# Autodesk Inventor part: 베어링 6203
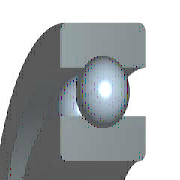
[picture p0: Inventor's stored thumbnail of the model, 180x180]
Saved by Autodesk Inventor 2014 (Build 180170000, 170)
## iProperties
IsCustomPart: 1
Created: 2012-02
Part Number: 베어링 6203
Material: 강철, 연강
Description: 깊은 그루브 볼 베어링
Document SubType Name: Modeling
Standard: KS B 2023
Designer: mduedu
Standards Organization: KS
Language: ko-KR
Size Designation: 6203 - 17 x 40 x 12
Categories: <MemberInstance><Categories><Category DisplayName="샤프트 부품" InternalName="7f7aeb1f-a693-4053-b835-cee3144e0d98" Mnemonic="SHFT"><Category DisplayName="베어링" Inter
Density: 1 g/cm^3
Appearance: Yellow
Author: mduedu
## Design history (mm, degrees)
sketch "스케치" dims "d0" = 5.98 (= -0.26 x WD + 0.26 x BD)
  geometry: L1 (3.01, 14.25)-(8.99, 14.25); L2 (6, 14.25)-(6, 11.26); L3 (6, 14.25)-(6, 17.24); L4 (3.778, 12.249)-(0, 12.249); L5 (0, 8.5)-(12, 8.5); L6 (3.778, 16.251)-(0, 16.251); L7 (0, 20)-(12, 20); L8 (12, 8.5)-(12, 12.249); L9 (8.222, 12.249)-(12, 12.249); L10 (8.222, 16.251)-(12, 16.251); L11 (12, 20)-(12, 16.251); L12 (-1.4, 0)-(8.4, 0) reference; L13 (0, -0.3)-(0, 5.3) reference
  constraints: 22 end point, 4 point on line, 2 collinear, 2 perpendicular, 2 symmetric about line, 1 midpoint, 1 parallel, 14 other
  dimensions: "d9" = 17 diameter of L5 L12 (= WD); "d11" = 40 diameter of L7 L12 (= BD); "d12" = 12 distance between parallel lines of L8 L13 (= KB); "d13" = 24.498 diameter of L9 L12 (= 0.326 x BD + 0.674 x WD)
revolve "본체" stored, may be unused: angle "d6" = 90 deg
revolve "볼" stored, may be unused: angle "d7" = 90 deg
pattern_circular "IDS_ARRAYBALL[SIMPL:T]" dims angle "d3" = 360 deg
body "Solid1"
fillet "모깎기1" dims "d1" = 0.6 (= KRS)
other parameters: "WD" = 17 [user parameter; used in 5 equation terms], "BD" = 40 [user parameter; used in 5 equation terms], "KB" = 12 [user parameter; used in 1 equation term], "KRS" = 0.6 [user parameter; used in 1 equation term], "d4" = 0, "d5" = 0, "d8" = 0, "d14" = 0, "d15" = 0, "BBA" = 0 [user parameter], "BC0" = 4750000 [user parameter], "BC" = 9560000 [user parameter], "WR" = 8.5 (= 0.5 x WD) [user parameter]
